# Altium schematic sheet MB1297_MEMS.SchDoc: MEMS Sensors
size A4; Date: Not used; ApprovedBy: Not used; CheckedBy: Not used; Author: Not used; CompanyName: STMicroelectronics; DrawnBy: Not used; Engineer: Not used; Organization: Not used; Address1: Not used; Address2: Not used; Address3: Not used; Address4: Not used; DocumentNumber: Not used; Revision: Not used; SheetNumber: 7; SheetTotal: 12
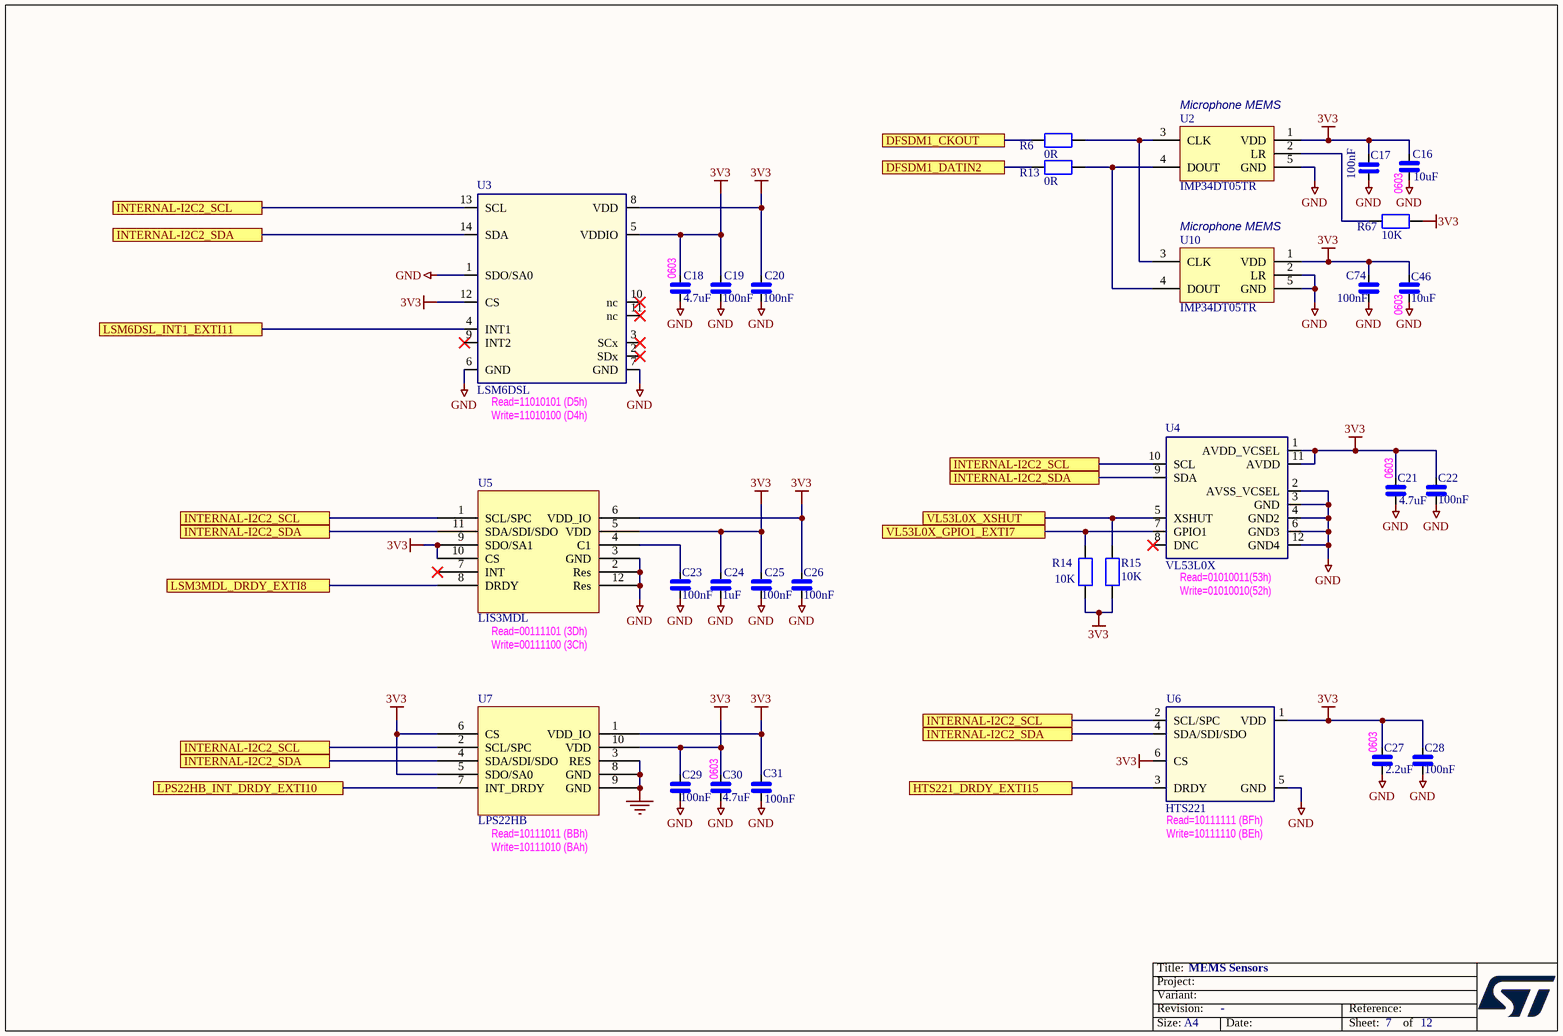
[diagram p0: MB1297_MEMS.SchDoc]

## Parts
C16  10uF  [0603_CAP_NPOL]
C17  100nF  [0402]
C18  4.7uF  [0603_CAP_NPOL]
C19  100nF  [0402]
C20  100nF  [0402]
C21  4.7uF  [0603_CAP_NPOL]
C22  100nF  [0402]
C23  100nF  [0402]
C24  1uF  [0402]
C25  100nF  [0402]
C26  100nF  [0402]
C27  2.2uF  [0603_CAP_NPOL]
C28  100nF  [0402]
C29  100nF  [0402]
C30  4.7uF  [0603_CAP_NPOL]
C31  100nF  [0402]
C46  10uF  [0603_CAP_NPOL]
C74  100nF  [0402]
R6  0R  [0402]
R13  0R  [0402]
R14  10K  [0402]
R15  10K  [0402]
R67  10K  [0402]
U2  IMP34DT05TR  [HCLGA-4LD 3x4x1]
U3  LSM6DSL  [LGA14L-2.5X3X0.86p0.5]
U4  VL53L0X  [LGA12-optical]
U5  LIS3MDL  [VFLGA12-2x2x1]
U6  HTS221  [HLGA6L-2x2x0.9]
U7  LPS22HB  [HLGA10L-2X2X0.76]
U10  IMP34DT05TR  [HCLGA-4LD 3x4x1]

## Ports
DFSDM1_CKOUT, DFSDM1_DATIN2, HTS221_DRDY_EXTI15, INTERNAL-I2C2_SCL, INTERNAL-I2C2_SDA, LPS22HB_INT_DRDY_EXTI10, LSM3MDL_DRDY_EXTI8, LSM6DSL_INT1_EXTI11, VL53L0X_GPIO1_EXTI7, VL53L0X_XSHUT

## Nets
3V3: C16.1 C17.2 C18.1 C19.1 C20.1 C21.1 C22.1 C24.1 C25.1 C26.1 C27.1 C28.1 C29.1 C30.1 C31.1 C46.1 C74.1 R14.1 R15.1 R67.1 U2.1(VDD) U3.5(VDDIO) U3.8(VDD) U3.12(CS) U4.1(AVDD_VCSEL) U4.11(AVDD) U5.5(VDD) U5.6(VDD_IO) U5.9(SDO/SA1) U5.10(CS) U6.1(VDD) U6.6(CS) U7.1(VDD_IO) U7.5(SDO/SA0) U7.6(CS) U7.10(VDD) U10.1(VDD)
GND: C16.2 C17.1 C18.2 C19.2 C20.2 C21.2 C22.2 C23.2 C24.2 C25.2 C26.2 C27.2 C28.2 C29.2 C30.2 C31.2 C46.2 C74.2 U2.5(GND) U3.1(SDO/SA0) U3.6(GND) U3.7(GND) U4.2(AVSS_VCSEL) U4.3(GND) U4.4(GND2) U4.6(GND3) U4.12(GND4) U5.2(Res) U5.3(GND) U5.12(Res) U6.5(GND) U7.3(RES) U7.8(GND) U7.9(GND) U10.2(LR) U10.5(GND)
DFSDM1_CKOUT: R6.2 ; port DFSDM1_CKOUT
DFSDM1_DATIN2: R13.2 ; port DFSDM1_DATIN2
HTS221_DRDY_EXTI15: U6.3(DRDY) ; port HTS221_DRDY_EXTI15
INTERNAL-I2C2_SCL: U3.13(SCL) U4.10(SCL) U5.1(SCL/SPC) U6.2(SCL/SPC) U7.2(SCL/SPC) ; port INTERNAL-I2C2_SCL
INTERNAL-I2C2_SDA: U3.14(SDA) U4.9(SDA) U5.11(SDA/SDI/SDO) U6.4(SDA/SDI/SDO) U7.4(SDA/SDI/SDO) ; port INTERNAL-I2C2_SDA
LPS22HB_INT_DRDY_EXTI10: U7.7(INT_DRDY) ; port LPS22HB_INT_DRDY_EXTI10
LSM3MDL_DRDY_EXTI8: U5.8(DRDY) ; port LSM3MDL_DRDY_EXTI8
LSM6DSL_INT1_EXTI11: U3.4(INT1) ; port LSM6DSL_INT1_EXTI11
VL53L0X_GPIO1_EXTI7: R14.2 U4.7(GPIO1) ; port VL53L0X_GPIO1_EXTI7
VL53L0X_XSHUT: R15.2 U4.5(XSHUT) ; port VL53L0X_XSHUT
NetC23_1: C23.1 U5.4(C1)
NetR6_1: R6.1 U2.3(CLK) U10.3(CLK)
NetR13_1: R13.1 U2.4(DOUT) U10.4(DOUT)
NetR67_2: R67.2 U2.2(LR)

Not connected (* = marked no-connect by the designer): U3 2(SDx)* 3(SCx)* 9(INT2)* 10(nc)* 11(nc)*; U4 8(DNC)*; U5 7(INT)*

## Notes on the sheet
- (near U2) Microphone MEMS
- (near U10) Microphone MEMS
- (near C16) 0603
- (near C18) 0603
- (near C46) 0603
- (near U3) Read=11010101 (D5h)
- (near U3) Write=11010100 (D4h)
- (near C21) 0603
- (near U4) Read=01010011(53h)
- (near U5) Read=00111101 (3Dh)
- Write=00111100 (3Ch)
- (near U4) Write=01010010(52h)
- (near C30) 0603
- (near C27) 0603
- (near U7) Read=10111011 (BBh)
- Write=10111010 (BAh)
- (near U6) Read=10111111 (BFh)
- (near U6) Write=10111110 (BEh)

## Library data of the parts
C16-C31 C46 C74 = CAP_NPOL: Capacitor_not polarized
R6 R13-R15 R67 = RES: Resistor
U2 U10 = MP34DT01: MEMS audio microphone
U3 = LSM6DSL: Accelero + Gyro MEMS (6 Axis)
U4 = VL53L0X: Proximity sensor MEMS
U5 = LIS3MDL: IC,Sensor; Provider: MMCC; Vendor: ST
U6 = HTS221: Humidity + Temp MEMS
U7 = LPS22HB: IC,Sensor; Provider: MMCC; Vendor: ST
